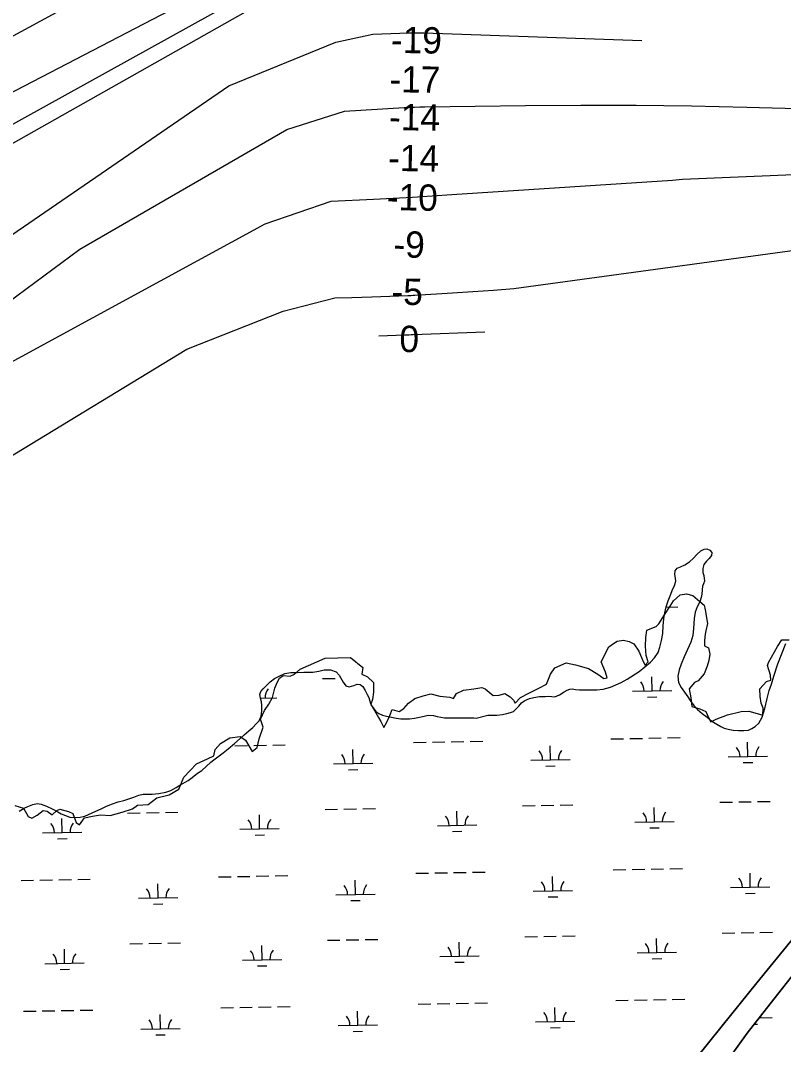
# Model space of a CAD drawing. Extents: x 3957609 to 3995875, y 234277 to 260273.
# Drawn here: x 3967195 to 3969134, y 243942 to 246545 of the extents above; entities that cross this region are included whole.
import ezdxf

# ---------------------------------------------------------------- set-up
doc = ezdxf.new("R2010")
doc.units = 0
for name, color, linetype in [('V-RIVR-EDGE', 7, 'Continuous'), ('V-RIVR-RANG', 7, 'Continuous'), ('V-TOPO-MINR', 7, 'Continuous'), ('V-TOPO-SHOR', 7, 'Continuous'), ('V-TOPO-WATR', 7, 'Continuous'), ('V-WETL-SWMP', 7, 'Continuous')]:
    doc.layers.add(name, color=color, linetype=linetype)

msp = doc.modelspace()

# ---------------------------------------------------------------- linework, layer by layer
at = {"layer": 'V-RIVR-EDGE'}
msp.add_lwpolyline([(3967180.187, 244548.963), (3967201.965, 244542.335), (3967214.275, 244521.504), (3967223.743, 244516.77), (3967236.999, 244524.345), (3967252.149, 244536.654), (3967262.565, 244534.76), (3967274.874, 244525.291), (3967287.183, 244536.654), (3967294.758, 244539.494), (3967316.536, 244533.813), (3967327.898, 244529.079), (3967336.42, 244506.354), (3967344.942, 244499.726), (3967357.251, 244517.716), (3967378.082, 244522.451), (3967397.966, 244525.291), (3967422.585, 244523.398), (3967452.885, 244531.919), (3967479.397, 244540.441), (3967491.706, 244549.91), (3967519.165, 244551.804), (3967540.943, 244568.847), (3967572.19, 244576.422), (3967596.808, 244590.625), (3967610.064, 244620.925), (3967642.258, 244655.012), (3967669.717, 244668.268), (3967685.813, 244675.843), (3967689.601, 244691.94), (3967702.857, 244707.09), (3967726.529, 244721.292), (3967753.041, 244725.08), (3967766.297, 244715.611), (3967783.34, 244686.258), (3967796.597, 244696.674), (3967801.331, 244718.452), (3967811.746, 244748.752), (3967805.118, 244768.636), (3967814.587, 244790.414), (3967825.949, 244806.51), (3967835.418, 244823.554), (3967841.099, 244847.226), (3967846.78, 244862.375), (3967853.409, 244872.791), (3967861.93, 244879.419), (3967879.921, 244878.472), (3967891.283, 244883.206), (3967905.486, 244895.516), (3967968.926, 244923.922), (3968033.313, 244925.815), (3968064.559, 244900.25), (3968062.666, 244883.206), (3968076.869, 244876.578), (3968092.018, 244862.375), (3968092.018, 244837.757), (3968089.178, 244818.82), (3968085.39, 244806.51), (3968104.328, 244773.37), (3968110.956, 244762.955), (3968118.531, 244747.805), (3968126.106, 244761.061), (3968133.681, 244778.104), (3968139.362, 244793.254), (3968157.352, 244788.52), (3968168.715, 244796.095), (3968181.024, 244809.351), (3968197.121, 244821.66), (3968217.952, 244828.288), (3968237.836, 244833.023), (3968260.56, 244827.341), (3968286.126, 244824.501), (3968295.594, 244821.66), (3968303.169, 244833.969), (3968321.16, 244842.491), (3968346.725, 244846.279), (3968367.556, 244849.119), (3968376.078, 244846.279), (3968395.962, 244829.235), (3968411.112, 244830.182), (3968426.262, 244833.969), (3968439.518, 244825.448), (3968448.04, 244816.926), (3968451.827, 244809.351), (3968466.03, 244823.554), (3968486.861, 244834.916), (3968512.427, 244847.226), (3968531.364, 244857.641), (3968541.779, 244883.206), (3968553.142, 244899.303), (3968581.548, 244911.612), (3968605.219, 244906.878), (3968638.36, 244897.409), (3968662.031, 244883.206), (3968677.181, 244871.844), (3968685.703, 244873.738), (3968681.915, 244887.941), (3968670.553, 244914.453), (3968690.437, 244952.328), (3968701.8, 244960.849), (3968711.268, 244967.477), (3968727.365, 244969.371), (3968741.568, 244966.531), (3968753.877, 244959.902), (3968766.186, 244941.912), (3968777.549, 244915.4), (3968782.283, 244905.931), (3968789.858, 244914.453), (3968785.124, 244930.55), (3968783.23, 244954.221), (3968784.177, 244975.999), (3968787.017, 244994.936), (3968810.689, 245004.405), (3968817.317, 245011.033), (3968831.52, 245033.758), (3968845.723, 245056.483), (3968854.245, 245069.739), (3968871.288, 245084.889), (3968887.385, 245087.729), (3968903.482, 245082.995), (3968921.472, 245067.845), (3968932.835, 245058.376), (3968934.728, 245047.014), (3968941.356, 245011.98), (3968936.622, 244993.043), (3968934.728, 244984.521), (3968933.782, 244968.424), (3968933.782, 244955.168), (3968943.25, 244950.434), (3968947.038, 244934.337), (3968944.197, 244918.24), (3968940.41, 244903.091), (3968932.835, 244884.153), (3968917.685, 244866.163), (3968908.216, 244862.375), (3968894.013, 244846.279), (3968898.748, 244822.607), (3968901.588, 244800.829), (3968921.472, 244795.148), (3968936.622, 244788.52), (3968943.25, 244773.37), (3968949.878, 244762.008), (3968963.134, 244768.636), (3968991.54, 244779.998), (3969026.574, 244788.52), (3969046.458, 244789.467), (3969061.608, 244784.732), (3969081.492, 244779.051), (3969082.439, 244797.042), (3969077.705, 244809.351), (3969074.864, 244826.394), (3969073.918, 244846.279), (3969090.961, 244864.269), (3969102.324, 244868.057), (3969101.377, 244880.366), (3969093.802, 244904.984), (3969095.695, 244912.559), (3969119.367, 244953.274), (3969129.783, 244970.318), (3969148.72, 244970.318)], dxfattribs=at)
at = {"layer": 'V-TOPO-MINR'}
for points in [[(3968181.084, 247052.195), (3965373.926, 245528.563), (3965228.884, 245429.671)], [(3968096.001, 246842.324), (3965395.806, 245438.803), (3965237.649, 245349.708), (3965234.899, 245347.738)], [(3968197.612, 246811.081), (3965557.117, 245319.444), (3965507.466, 245290.941), (3965389.501, 245210.055), (3965258.871, 245108.954)], [(3968102.887, 246796.068), (3966353.197, 245826.642), (3965752.679, 245530.856), (3965663.169, 245477.445), (3965402.799, 245332.334), (3965242.482, 245232.395)], [(3965334.242, 244565.003), (3965447.5, 244634.66), (3965466.336, 244646.125), (3965485.243, 244657.472), (3965504.253, 244668.644), (3966606.154, 245612.18), (3967724.041, 246379.376), (3967996.583, 246490.295), (3968090.356, 246510.845)], [(3968090.356, 246510.845), (3968182.197, 246513.752), (3968191.686, 246513.958), (3968201.174, 246514.037), (3968210.661, 246513.927), (3968220.149, 246513.691), (3968774.119, 246494.368)], [(3968018.214, 246314.387), (3968169.95, 246323.752), (3968183.086, 246324.466), (3968196.227, 246325.051), (3968209.375, 246325.442), (3968222.528, 246325.705), (3968477.968, 246328.931), (3968618.838, 246329.888), (3968759.702, 246329.746), (3968900.553, 246327.959), (3969041.398, 246325.074), (3970886.166, 246276.501), (3970886.6, 246276.508), (3970887.46, 246276.621), (3970887.884, 246276.714), (3971224.276, 246358.726)], [(3965336.203, 244483.843), (3965432.433, 244550.968), (3965464.151, 244572.47), (3965496.234, 244593.396), (3965528.864, 244613.459), (3965561.858, 244632.947), (3965595.241, 244651.79), (3965666.539, 244717.388), (3965834.719, 244844.984), (3967345.253, 245963.426), (3967871.86, 246268.456), (3968018.214, 246314.387)], [(3967984.26, 246085.689), (3968092.213, 246090.995), (3968141.873, 246093.558), (3968191.524, 246096.284), (3968241.162, 246099.254), (3968290.79, 246102.387), (3968851.891, 246139.195), (3968877.6, 246141.493), (3970879.56, 246225.354), (3970881.146, 246225.397), (3970884.286, 246225.855), (3970885.836, 246226.204), (3971195.807, 246303.452)], [(3967993.694, 245839.928), (3968037.136, 245840.981), (3968087.474, 245842.556), (3968178.984, 245845.901), (3968183.56, 245846.084), (3968188.135, 245846.289), (3968192.709, 245846.525), (3968197.281, 245846.782), (3968292.438, 245852.461), (3968344.567, 245855.838), (3968396.67, 245859.567), (3968448.732, 245863.824), (3970882.382, 246196.277), (3970883.256, 246197.118), (3970883.849, 246197.376), (3970910.475, 246204.139), (3970924.528, 246207.257), (3970938.667, 246209.799), (3970952.935, 246211.476), (3970967.288, 246212.578), (3971208.52, 246223.719)], [(3965384.711, 244461.903), (3965486.509, 244525.473), (3965495.836, 244531.125), (3965505.26, 244536.606), (3965514.828, 244541.832), (3965524.491, 244546.886), (3966098.023, 244932.795), (3966287.417, 245048.337), (3967026.516, 245598.315), (3967816.428, 246028.129), (3967984.26, 246085.689)], [(3966834.79, 244858.74), (3966740.115, 245006.742), (3966758.593, 245057.58), (3967160.478, 245431.935), (3967617.795, 245709.235), (3967862.622, 245806.289), (3967993.694, 245839.928)]]:
    msp.add_lwpolyline(points, dxfattribs=at)
at = {"layer": 'V-TOPO-SHOR'}
for points in [[(3968909.009, 243902.514), (3968978.145, 243989.028), (3969066.328, 244098.768), (3969160.923, 244213.361)], [(3969188.554, 244156.986), (3969109.631, 244056.698), (3969042.04, 243970.161), (3968975.128, 243877.123)]]:
    msp.add_lwpolyline(points, dxfattribs=at)
at = {"layer": 'V-TOPO-WATR'}
msp.add_lwpolyline([(3968105.249, 245743.038), (3968171.527, 245745.915), (3968176.927, 245746.145), (3968182.328, 245746.372), (3968187.73, 245746.591), (3968193.131, 245746.805), (3968374.906, 245753.903)], dxfattribs=at)
at = {"layer": 'V-WETL-SWMP'}
for p, q in [((3968836.193, 245053.827), (3968865.44, 245054.358)), ((3967962.703, 244871.742), (3967994.697, 244872.324)), ((3968800.16, 244840.532), (3968799.506, 244876.526)), ((3968750.169, 244839.623), (3968850.152, 244841.441)), ((3967804.611, 244822.43), (3967846.502, 244823.192)), ((3967807.666, 244807.052), (3967808.789, 244807.072)), ((3968788.443, 244824.886), (3968812.439, 244825.322)), ((3967739.859, 244701.162), (3967771.854, 244701.744)), ((3967787.851, 244702.034), (3967819.846, 244702.616)), ((3967835.843, 244702.907), (3967867.838, 244703.489)), ((3968193.692, 244709.414), (3968225.687, 244709.996)), ((3968241.684, 244710.287), (3968273.679, 244710.868)), ((3968289.676, 244711.159), (3968321.671, 244711.741)), ((3968337.668, 244712.032), (3968369.663, 244712.614)), ((3968541.873, 244664.994), (3968541.218, 244700.989)), ((3968695.517, 244718.539), (3968727.512, 244719.12)), ((3968743.509, 244719.411), (3968775.504, 244719.993)), ((3968791.501, 244720.284), (3968823.496, 244720.866)), ((3968839.493, 244721.157), (3968871.488, 244721.738)), ((3969043.698, 244674.119), (3969043.044, 244710.113)), ((3968040.048, 244655.87), (3968039.393, 244691.864)), ((3968993.706, 244673.21), (3969093.69, 244675.028)), ((3967990.056, 244654.961), (3968090.04, 244656.779)), ((3968491.881, 244664.085), (3968591.865, 244665.904)), ((3968530.155, 244649.348), (3968554.151, 244649.784)), ((3969031.981, 244658.473), (3969055.977, 244658.909)), ((3968028.33, 244640.223), (3968052.326, 244640.659)), ((3968064.735, 244540.868), (3968096.729, 244541.449)), ((3968470.576, 244548.247), (3968502.57, 244548.829)), ((3968518.568, 244549.12), (3968550.562, 244549.701)), ((3968566.56, 244549.992), (3968598.554, 244550.574)), ((3968806.208, 244507.912), (3968805.554, 244543.906)), ((3968972.401, 244557.372), (3969004.395, 244557.953)), ((3969020.393, 244558.244), (3969052.387, 244558.826)), ((3969068.385, 244559.117), (3969100.38, 244559.699)), ((3967300.733, 244480.538), (3967300.079, 244516.532)), ((3967466.926, 244529.998), (3967498.92, 244530.579)), ((3967514.918, 244530.87), (3967546.912, 244531.452)), ((3967562.91, 244531.743), (3967594.904, 244532.325)), ((3967802.558, 244489.663), (3967801.904, 244525.657)), ((3967968.751, 244539.122), (3968000.745, 244539.704)), ((3968016.743, 244539.995), (3968048.737, 244540.577)), ((3968304.383, 244498.787), (3968303.729, 244534.781)), ((3967752.567, 244488.754), (3967852.55, 244490.572)), ((3968254.392, 244497.878), (3968354.375, 244499.696)), ((3968756.217, 244507.003), (3968856.2, 244508.821)), ((3968794.491, 244492.266), (3968818.487, 244492.702)), ((3967250.742, 244479.629), (3967350.725, 244481.447)), ((3967289.016, 244464.891), (3967313.012, 244465.328)), ((3967790.841, 244474.016), (3967814.837, 244474.452)), ((3968292.666, 244483.141), (3968316.662, 244483.577)), ((3968701.565, 244385.919), (3968733.56, 244386.5)), ((3968749.557, 244386.791), (3968781.552, 244387.373)), ((3968797.549, 244387.664), (3968829.544, 244388.246)), ((3968845.541, 244388.537), (3968877.536, 244389.118)), ((3967244.082, 244359.417), (3967276.077, 244359.999)), ((3967292.074, 244360.29), (3967324.069, 244360.871)), ((3967340.066, 244361.162), (3967372.061, 244361.744)), ((3967697.915, 244367.669), (3967729.91, 244368.251)), ((3967745.907, 244368.542), (3967777.902, 244369.124)), ((3967793.899, 244369.414), (3967825.894, 244369.996)), ((3967841.891, 244370.287), (3967873.886, 244370.869)), ((3968046.096, 244323.25), (3968045.441, 244359.244)), ((3968199.74, 244376.794), (3968231.735, 244377.376)), ((3968247.732, 244377.667), (3968279.727, 244378.248)), ((3968295.724, 244378.539), (3968327.719, 244379.121)), ((3968343.716, 244379.412), (3968375.711, 244379.994)), ((3968547.921, 244332.374), (3968547.267, 244368.369)), ((3969049.746, 244341.499), (3969049.092, 244377.493)), ((3967196.09, 244358.544), (3967228.085, 244359.126)), ((3967544.271, 244314.125), (3967543.616, 244350.119)), ((3968497.929, 244331.465), (3968597.913, 244333.283)), ((3968999.754, 244340.59), (3969099.738, 244342.408)), ((3967494.279, 244313.216), (3967594.263, 244315.034)), ((3967996.104, 244322.341), (3968096.088, 244324.159)), ((3968034.378, 244307.603), (3968058.375, 244308.039)), ((3968536.204, 244316.728), (3968560.2, 244317.164)), ((3969038.029, 244325.853), (3969062.025, 244326.289)), ((3967532.553, 244298.478), (3967556.549, 244298.915)), ((3967974.799, 244206.502), (3968006.793, 244207.084)), ((3968022.791, 244207.375), (3968054.785, 244207.957)), ((3968070.783, 244208.248), (3968102.777, 244208.829)), ((3968476.624, 244215.627), (3968508.618, 244216.209)), ((3968524.616, 244216.5), (3968556.61, 244217.081)), ((3968572.608, 244217.372), (3968604.603, 244217.954)), ((3968812.256, 244175.292), (3968811.602, 244211.286)), ((3968978.449, 244224.752), (3969010.443, 244225.333)), ((3969026.441, 244225.624), (3969058.436, 244226.206)), ((3969074.433, 244226.497), (3969106.428, 244227.079)), ((3967306.781, 244147.918), (3967306.127, 244183.912)), ((3967472.974, 244197.378), (3967504.968, 244197.959)), ((3967520.966, 244198.25), (3967552.96, 244198.832)), ((3967568.958, 244199.123), (3967600.952, 244199.705)), ((3967808.606, 244157.043), (3967807.952, 244193.037)), ((3968310.431, 244166.167), (3968309.777, 244202.161)), ((3967758.615, 244156.134), (3967858.598, 244157.952)), ((3968260.44, 244165.258), (3968360.423, 244167.076)), ((3968298.714, 244150.521), (3968322.71, 244150.957)), ((3968762.265, 244174.383), (3968862.248, 244176.201)), ((3968800.539, 244159.646), (3968824.535, 244160.082)), ((3967256.79, 244147.009), (3967356.773, 244148.827)), ((3967295.064, 244132.271), (3967319.06, 244132.708)), ((3967796.889, 244141.396), (3967820.885, 244141.832)), ((3968349.764, 244046.792), (3968381.759, 244047.374)), ((3968707.613, 244053.299), (3968739.608, 244053.88)), ((3968755.605, 244054.171), (3968787.6, 244054.753)), ((3968803.597, 244055.044), (3968835.592, 244055.626)), ((3968851.589, 244055.916), (3968883.584, 244056.498)), ((3967202.138, 244025.924), (3967234.133, 244026.506)), ((3967250.13, 244026.797), (3967282.125, 244027.379)), ((3967298.122, 244027.67), (3967330.117, 244028.251)), ((3967346.114, 244028.542), (3967378.109, 244029.124)), ((3967703.963, 244035.049), (3967735.958, 244035.631)), ((3967751.955, 244035.922), (3967783.95, 244036.504)), ((3967799.947, 244036.794), (3967831.942, 244037.376)), ((3967847.939, 244037.667), (3967879.934, 244038.249)), ((3968052.144, 243990.63), (3968051.49, 244026.624)), ((3968205.788, 244044.174), (3968237.783, 244044.756)), ((3968253.78, 244045.046), (3968285.775, 244045.628)), ((3968301.772, 244045.919), (3968333.767, 244046.501)), ((3968553.969, 243999.754), (3968553.315, 244035.749)), ((3967550.319, 243981.505), (3967549.664, 244017.499)), ((3968503.977, 243998.845), (3968603.961, 244000.663)), ((3969072.519, 244009.183), (3969105.786, 244009.788)), ((3967500.327, 243980.596), (3967600.311, 243982.414)), ((3968002.152, 243989.721), (3968102.136, 243991.539)), ((3968040.427, 243974.983), (3968064.423, 243975.419)), ((3968542.252, 243984.108), (3968566.248, 243984.544)), ((3969060.29, 243993.527), (3969068.073, 243993.669)), ((3967538.601, 243965.858), (3967562.598, 243966.295))]:
    msp.add_line(p, q, dxfattribs=at)
for points in [[(3967952.84, 244890.889), (3967966.218, 244893.765), (3967982.492, 244893.964), (3967996.869, 244889.016), (3968004.96, 244880.524), (3968014.518, 244863.009), (3968021.413, 244853.749), (3968030.187, 244850.993), (3968042.052, 244854.303), (3968050.604, 244857.422), (3968057.997, 244856.759), (3968064.543, 244851.413), (3968070.394, 244841.237), (3968075.786, 244831.658), (3968079.799, 244823.87), (3968082.475, 244814.559), (3968084.057, 244808.4), (3968085.299, 244805.401), (3968093.273, 244794.195), (3968098.319, 244788.229), (3968105.159, 244783.49), (3968114.861, 244778.786), (3968124.841, 244776.045), (3968137.379, 244773.636), (3968149.313, 244771.37), (3968161.694, 244769.412), (3968172.999, 244769.249), (3968183.396, 244769.376), (3968196.18, 244771.491), (3968209.109, 244774.06), (3968220.383, 244776.459), (3968231.055, 244778.699), (3968244.172, 244778.257), (3968254, 244775.664), (3968263.515, 244773.972), (3968272.881, 244772.127), (3968284.937, 244772.124), (3968292.019, 244772.21), (3968301.514, 244772.176), (3968311.761, 244772.301), (3968326.377, 244772.48), (3968339.488, 244772.489), (3968346.879, 244771.977), (3968352.766, 244771.144), (3968382.213, 244778.587), (3968394.115, 244778.884), (3968405.565, 244779.174), (3968419.867, 244780.404), (3968430.687, 244782.948), (3968439.845, 244785.772), (3968447.497, 244788.578), (3968454.807, 244794.696), (3968461.35, 244801.859), (3968468.325, 244810.685), (3968476.846, 244816.365), (3968488.842, 244821.334), (3968499.514, 244823.575), (3968513.952, 244826.012), (3968528.561, 244826.793), (3968538.048, 244827.361), (3968552.988, 244825.735), (3968564.704, 244830.225), (3968576.465, 244838.129), (3968583.976, 244842.365), (3968591.156, 244845.209), (3968596.906, 244845.747), (3968605.424, 244844.536), (3968615.963, 244843.607), (3968645.131, 244843.029), (3968659.412, 244843.287), (3968676.044, 244845.063), (3968694.114, 244849.766), (3968721.758, 244861.78), (3968736.628, 244870.565), (3968767.175, 244890.142), (3968795.921, 244913.934), (3968806.636, 244925.107), (3968815.361, 244938.172), (3968820.062, 244951.916), (3968824.494, 244968.612), (3968827.553, 244986.88), (3968828.3, 245006.268), (3968829.951, 245023.781), (3968832.807, 245038.793), (3968836.291, 245054.262), (3968841.174, 245069.865), (3968847.626, 245086.687), (3968851.487, 245096.098), (3968857.257, 245108.74), (3968860.208, 245119.561), (3968859.702, 245127.483), (3968858.128, 245136.662), (3968859.192, 245145.803), (3968864.101, 245152.56), (3968872.219, 245155.856), (3968883.622, 245160.967), (3968895.37, 245168.401), (3968905.129, 245177.881), (3968913.798, 245187.067), (3968924.334, 245196.535), (3968932.157, 245200.922)], [(3968932.157, 245200.922), (3968939.468, 245202.058), (3968947.174, 245198.376), (3968951.898, 245192.411), (3968951.32, 245184.659), (3968945.626, 245177.293), (3968938.383, 245170.104), (3968931.904, 245162.128), (3968928.8, 245151.465), (3968929.592, 245141.832), (3968931.804, 245133.885), (3968933.301, 245119.43), (3968931.032, 245112.79), (3968928.462, 245106.775), (3968927.092, 245097.949), (3968926.775, 245086.779), (3968924.627, 245077.809), (3968921.215, 245067.306), (3968914.979, 245054.671), (3968909.969, 245040.932), (3968907.097, 245024.833), (3968905.643, 244999.558), (3968903.835, 244981.893), (3968898.312, 244964.902), (3968881.621, 244926.967), (3968874.065, 244908.919), (3968868.723, 244893.788), (3968865.397, 244878.472), (3968867.639, 244861.834), (3968873.82, 244849.329), (3968891.165, 244825.488), (3968897.243, 244816.554), (3968906.678, 244803.691), (3968915.689, 244793.628), (3968927.336, 244783.527), (3968939.918, 244773.567), (3968951.88, 244763.771), (3968964.646, 244755.826), (3968975.111, 244749.777), (3968983.584, 244745.464), (3968993.17, 244742.996), (3969006.014, 244740.482), (3969019.504, 244739.665), (3969033.471, 244739.618), (3969044.975, 244741.003), (3969054.033, 244744.906), (3969061.863, 244749.758), (3969071.924, 244758.613), (3969080.373, 244774.01), (3969086.436, 244796.114), (3969092.546, 244821.477), (3969097.802, 244841.42), (3969103.631, 244858.096), (3969109.658, 244877.718), (3969119.74, 244909.386), (3969140.36, 244961.386)], [(3967191.313, 244534.81), (3967203.884, 244542.047), (3967213.474, 244546.535), (3967226.368, 244551.967), (3967236.736, 244554.505), (3967247.002, 244552.973), (3967260.478, 244547.863), (3967275.178, 244541.11), (3967289.139, 244533.293), (3967297.939, 244528.428), (3967308.7, 244523.435), (3967320.053, 244519.354), (3967330.764, 244518.43), (3967346.573, 244519.678), (3967353.791, 244520.972), (3967357.995, 244522.229), (3967385.717, 244535.227), (3967399.359, 244541.121), (3967413.148, 244547.317), (3967428.289, 244553.832), (3967443.001, 244558.533), (3967457.277, 244561.872), (3967482.94, 244570.625), (3967495.388, 244575.6), (3967506.66, 244578.149), (3967516.607, 244578.12), (3967529.262, 244578.425), (3967546.125, 244579.686), (3967564.472, 244582.925), (3967576.625, 244587.293), (3967590.098, 244594.692), (3967599.97, 244600.84), (3967620.773, 244612.699), (3967631.074, 244620.661), (3967644.358, 244631.222), (3967655.427, 244637.989), (3967678.525, 244659.37), (3967686.29, 244665.191), (3967695.993, 244672.845), (3967709.581, 244683.108), (3967722.716, 244693.517), (3967738.376, 244706.97), (3967753.14, 244719.659), (3967763.421, 244729.279), (3967775.205, 244739.219), (3967784.904, 244747.174), (3967793.983, 244756.478), (3967801.267, 244764.705), (3967806.395, 244776.673), (3967808.345, 244789.809), (3967808.038, 244802.615), (3967807.155, 244813.153), (3967804.632, 244822.315), (3967803.016, 244831.187), (3967805.938, 244838.758), (3967811.425, 244846.059), (3967818.123, 244852.922), (3967829.444, 244863.761), (3967840.043, 244872.028), (3967852.474, 244878.359), (3967866.866, 244884.563), (3967881.901, 244887.46), (3967897.72, 244887.804), (3967914.595, 244888.161), (3967924.843, 244888.135), (3967937.95, 244888.446), (3967952.84, 244890.889)], [(3969160.922, 244213.361), (3969066.328, 244098.767), (3968978.145, 243989.027), (3968909.008, 243902.513)], [(3968975.128, 243877.123), (3969042.04, 243970.162), (3969109.631, 244056.698), (3969188.554, 244156.986)]]:
    msp.add_lwpolyline(points, dxfattribs=at)
for centre, start, end in [((3968744.918, 244840.003), 0.269879, 41.813537), ((3968855.386, 244842.011), 140.269876, 181.813534), ((3967851.735, 244823.762), 140.269876, 181.813534), ((3969098.923, 244675.598), 140.269876, 181.813534), ((3967984.805, 244655.34), 0.269879, 41.813537), ((3968095.273, 244657.349), 140.269876, 181.813534), ((3968486.631, 244664.465), 0.269879, 41.813537), ((3968597.098, 244666.474), 140.269876, 181.813534), ((3968988.456, 244673.59), 0.269879, 41.813537), ((3968249.141, 244498.258), 0.269879, 41.813537), ((3968359.609, 244500.266), 140.269876, 181.813534), ((3968750.966, 244507.383), 0.269879, 41.813537), ((3968861.434, 244509.391), 140.269876, 181.813534), ((3967245.491, 244480.008), 0.269879, 41.813537), ((3967355.958, 244482.017), 140.269876, 181.813534), ((3967747.316, 244489.133), 0.269879, 41.813537), ((3967857.783, 244491.142), 140.269876, 181.813534), ((3968994.504, 244340.97), 0.269879, 41.813537), ((3969104.971, 244342.978), 140.269876, 181.813534), ((3967489.028, 244313.595), 0.269879, 41.813537), ((3967599.496, 244315.604), 140.269876, 181.813534), ((3967990.854, 244322.72), 0.269879, 41.813537), ((3968101.321, 244324.729), 140.269876, 181.813534), ((3968492.679, 244331.845), 0.269879, 41.813537), ((3968603.146, 244333.854), 140.269876, 181.813534), ((3967753.364, 244156.513), 0.269879, 41.813537), ((3967863.832, 244158.522), 140.269876, 181.813534), ((3968255.189, 244165.638), 0.269879, 41.813537), ((3968365.657, 244167.646), 140.269876, 181.813534), ((3968757.014, 244174.763), 0.269879, 41.813537), ((3968867.482, 244176.771), 140.269876, 181.813534), ((3967251.539, 244147.388), 0.269879, 41.813537), ((3967362.006, 244149.397), 140.269876, 181.813534), ((3968498.727, 243999.225), 0.269879, 41.813537), ((3968609.194, 244001.234), 140.269876, 181.813534), ((3967495.077, 243980.975), 0.269879, 41.813537), ((3967605.544, 243982.984), 140.269876, 181.813534), ((3967996.902, 243990.1), 0.269879, 41.813537), ((3968107.369, 243992.109), 140.269876, 181.813534), ((3969111.019, 244010.358), 174.831399, 181.813534)]:
    msp.add_arc(centre, 35.246, start, end, dxfattribs=at)

# ---------------------------------------------------------------- texts
at = {"layer": 'V-RIVR-RANG'}
for s, p in [('-19', (3968135.868, 246462.988)), ('-17', (3968131.889, 246363.027)), ('-14', (3968130.958, 246266.678)), ('-14', (3968128.708, 246162.928)), ('-10', (3968125.553, 246063.146)), ('-9', (3968142.305, 245942.833)), ('-5', (3968137.189, 245822.765)), ('0', (3968157.384, 245702.505))]:
    msp.add_text(s, height=67, rotation=359.009528, dxfattribs=at).set_placement(p)

doc.saveas('drawing.dxf')
